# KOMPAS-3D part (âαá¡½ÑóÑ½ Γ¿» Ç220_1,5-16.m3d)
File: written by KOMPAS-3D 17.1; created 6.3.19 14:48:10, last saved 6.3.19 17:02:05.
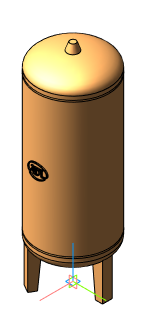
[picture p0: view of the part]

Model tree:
1. Операция без истории:1  (with: Сечение модели:1)

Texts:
  Гранлевел тип А100_1,5-16
  Гранлевел тип А150_1,5-16
  Гранлевел тип А220_1,5-16
  Гранлевел тип А350_1,5-16
  Гранлевел тип А500_1,5-16
  Гранлевел тип А700_1,5-16
  Гранлевел тип А900_1,5-16
  Гранлевел тип А1000_1,5-16
  Гранлевел тип А1400_1,5-16
  Точка начала. Х
  Точка начала. Y
  Точка начала. Z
